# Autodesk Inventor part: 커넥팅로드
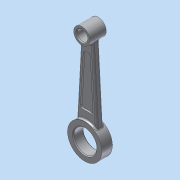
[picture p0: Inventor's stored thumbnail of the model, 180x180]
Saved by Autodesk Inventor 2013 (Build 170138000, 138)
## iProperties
Created: 2016-11
Part Number: 커넥팅로드
Material: 알루미늄 6061
Document SubType Name: Modeling
Designer: mduedu
Density: 1 g/cm^3
Mass: 23.9068 g
Surface Area: 114.14 cm^2
Volume: 23.9068 cm^3
Author: mduedu
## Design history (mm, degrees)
sketch "스케치1" dims "d0" = 42, "d3" = 20
  geometry: L1 (0, 0)-(0, 114); L2 (-7.5, 107.386)-(-12.5, 16.875); L3 (7.5, 107.386)-(12.5, 16.875); C1 r 14 at (0, 0); C2 r 6.5 at (0, 114); 3 further points
  constraints: 6 end point, 4 coincident, 2 centre point, 2 symmetric about line, 1 vertical, 6 other
  dimensions: "d1" = 28 diameter of C1; "d2" = 13 diameter of C2; "d4" = 114 distance of L1.start L1.end; "d6" = 12.5 distance from line of L1 L2.end; "d7" = 7.5 distance from line of L1 L2.start
extrude "돌출1" new body sketch "스케치1" stored distance "d8" = 13; taper "d9" = 0 deg
extrude "돌출2" join sketch "스케치1" stored distance "d10" = 20; taper "d11" = 0 deg
sketch "스케치2"
  geometry: L1 (-7.5, 107.386)-(-12.5, 16.875) reference; L2 (7.5, 107.386)-(12.5, 16.875) reference; A1 r 10 centre (0, 114) between (-7.5, 107.386) and (7.5, 107.386) reference; A2 r 21 centre (0, 0) between (-12.5, 16.875) and (12.5, 16.875) reference; 1 further point
extrude "돌출3" join sketch "스케치2" stored distance "d12" = 8; taper "d13" = 0 deg
sketch "스케치3"
  geometry: L1 (-7.5, 107.386)-(-12.5, 16.875) reference; L2 (7.5, 107.386)-(12.5, 16.875) reference; L3 (-4.209, 94.448)-(-7.768, 30.011); L4 (4.209, 94.448)-(7.768, 30.011); L5 (0, 94)-(0, 31); A1 r 10 centre (0, 114) between (-7.5, 107.386) and (7.5, 107.386) reference; A2 r 21 centre (0, 0) between (-12.5, 16.875) and (12.5, 16.875) reference; A3 r 20 centre (0, 114) between (-4.209, 94.448) and (4.209, 94.448); A4 r 31 centre (0, 0) between (7.768, 30.011) and (-7.768, 30.011); 1 further point
  constraints: 6 end point, 6 point on circle, 2 centre point, 2 parallel, 1 symmetric about line, 1 vertical alignment
  dimensions: "d18" = 10 radial gap between concentric circles of A3 A1; "d19" = 10 radial gap between concentric circles of A2 A4; "d20" = 4 distance between parallel lines of L3 L1
extrude "돌출4" cut sketch "스케치3" distance "d21" = 2; taper "d22" = 0 deg
fillet "모깎기1" dims "d23" = 3
fillet "모깎기2" dims "d24" = 2
fillet "모깎기3" dims "d25" = 2
chamfer "모따기1" distance "d26" = 1; stored, may be unused: second distance "d27" = 2, angle "d28" = 45 deg
node "솔리드1"
mirror "대칭1"
other parameters: "d16" = 4, "d17" = 4
